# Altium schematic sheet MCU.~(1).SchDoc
size A3; SheetNumber: 10; SheetTotal: 10
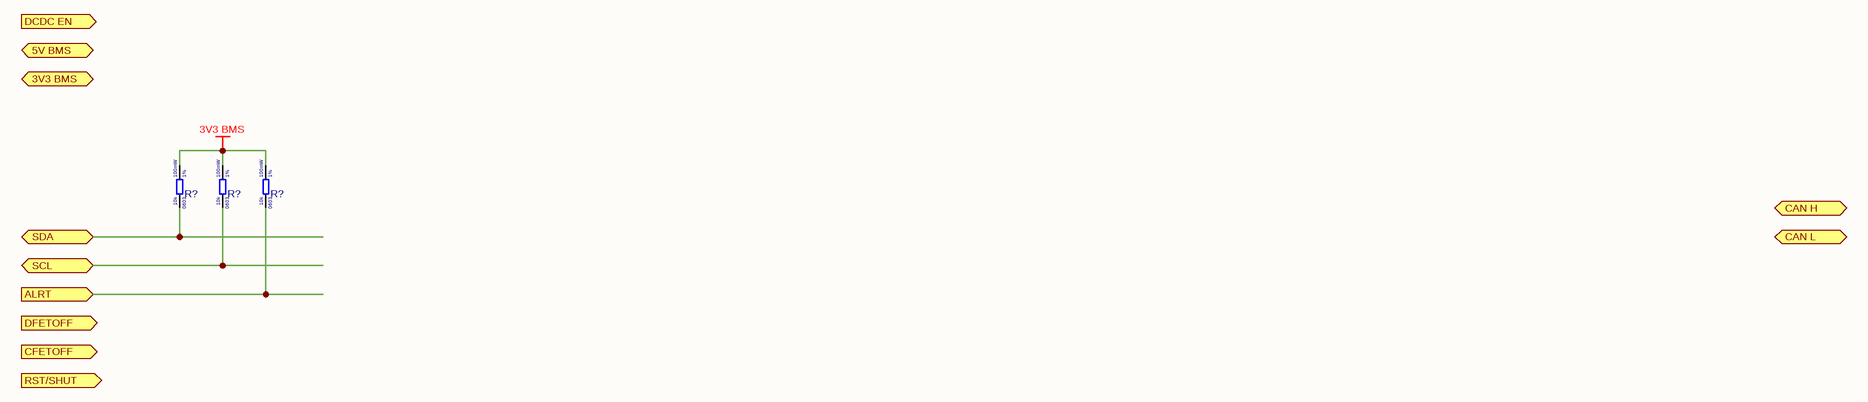
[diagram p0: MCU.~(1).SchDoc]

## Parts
(Parts that share a designator on the sheet are numbered #1, #2 ... from top to bottom, then left to right.)
R?#1  Resistance Tolerance: 1%  Resistance: 10k  Power Rating: 100mW  Case Code (Imperial): 0603  [RES_0603]  (hidden comment: 0603WAF1002T5E)
R?#2  Resistance Tolerance: 1%  Resistance: 10k  Power Rating: 100mW  Case Code (Imperial): 0603  [RES_0603]  (hidden comment: 0603WAF1002T5E)
R?#3  Resistance Tolerance: 1%  Resistance: 10k  Power Rating: 100mW  Case Code (Imperial): 0603  [RES_0603]  (hidden comment: 0603WAF1002T5E)

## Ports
3V3 BMS (bidir, see BMS[4B]), 5V BMS (bidir, see BMS[4B]), ALRT (in, see BMS[4B], BQ76952 BMS[7C]), CAN H (bidir, see BMS[4B], BMS[8B]), CAN L (bidir, see BMS[4B], BMS[8B]), CFETOFF (out, see BMS[4C], BQ76952 BMS[7C]), DCDC EN (out, see BMS[4B]), DFETOFF (out, see BMS[4B], BQ76952 BMS[7C]), RST/SHUT (out, see BMS[4B], BQ76952 BMS[7C]), SCL (bidir, see BMS[4C], BMS[8C], BQ76952 BMS[7C]), SDA (bidir, see BMS[4C], BMS[8C], BQ76952 BMS[7C])

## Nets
3V3 BMS: R?#1.2 R?#2.2 R?#3.2
ALRT: R?#3.1 ; port ALRT
SCL: R?#2.1 ; port SCL
SDA: R?#1.1 ; port SDA

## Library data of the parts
R?#1-R?#3 = 0603WAF1002T5E: Res 10k 0603 1% 100mW 75V; Manufacturer: Uni-Royal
